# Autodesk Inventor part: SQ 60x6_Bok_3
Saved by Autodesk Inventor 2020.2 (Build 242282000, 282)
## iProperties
Created: 2006-08
Part Number: SQ 60x6_Bok_3
Material: Ogólny
Document SubType Name: Modeling
Designer: F.Stasiak
Manufacturer: Standard
Standards Organization: Custom
Stock Number: DIN EN 10210-2 SQ 60x6
Density: 1 g/cm^3
Appearance: Domyślna
Manager: www.cadconsulting.pl
Company: Fabian Stasiak CAD Consulting
G_L: 767,1 mm
G_W: 60,000 mm
G_H: 60,000 mm
AFG_Item: 60 x 60 x 6
Author: F.Stasiak
Subject: Zbiór ćwiczeń. Autodesk Inventor 2020. Kurs podstawowy
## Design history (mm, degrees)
sketch "AFG_Detailed"
  geometry: L1 (-12, 54)-(-48, 54); L2 (-54, 48)-(-54, 12); L3 (-48, 6)-(-12, 6); L4 (-6, 12)-(-6, 48); L5 (-12, 60)-(-48, 60); L6 (-60, 48)-(-60, 12); L7 (-48, 0)-(-12, 0); L8 (0, 12)-(0, 48); A1 r 6 centre (-12, 48) between (-6, 48) and (-12, 54); A2 r 12 centre (-12, 48) between (0, 48) and (-12, 60); A3 r 6 centre (-12, 12) between (-12, 6) and (-6, 12); A4 r 12 centre (-12, 12) between (-12, 0) and (0, 12); A5 r 12 centre (-48, 12) between (-60, 12) and (-48, 0); A6 r 6 centre (-48, 12) between (-54, 12) and (-48, 6); A7 r 6 centre (-48, 48) between (-48, 54) and (-54, 48); A8 r 12 centre (-48, 48) between (-48, 60) and (-60, 48); 4 further points
  constraints: 16 end point, 16 point on circle, 16 tangent, 8 centre point, 6 point on line, 4 parallel, 2 perpendicular, 1 vertical
  dimensions: "d15" = 60 distance of point (-60, 0) point (0, 0) (= GEO_B); "d16" = 6 distance between parallel lines of L7 L3 (= GEO_S); "d17" = 6 distance between parallel lines of L8 L4 (= GEO_S); "d18" = 6 distance between parallel lines of L5 L1 (= GEO_S); "d19" = 6 distance between parallel lines of L6 L2 (= GEO_S); "d20" = 30 distance from line of point (-30, 30) L7 (= 0.5 x GEO_H); "d30" = 6 radius of A1 (= GEO_R1 - GEO_S); "GEO_R1" = 12 radius of A2; "d32" = 6 radius of A3 (= GEO_R1 - GEO_S); "d33" = 12 radius of A4 (= GEO_R1); "d34" = 12 radius of A5 (= GEO_R1); "d35" = 6 radius of A6 (= GEO_R1 - GEO_S); "d36" = 6 radius of A7 (= GEO_R1 - GEO_S); "d37" = 12 radius of A8 (= GEO_R1); "d38" = 30 distance from line of L6 point (-30, 30) (= 0.5 x GEO_B); "d39" = 60 distance between parallel lines of L7 L5 (= GEO_H)
sketch "AFG_Medium"
  geometry: L1 (-6, 54)-(-54, 54); L2 (-54, 54)-(-54, 6); L3 (-54, 6)-(-6, 6); L4 (-6, 6)-(-6, 54); L5 (0, 60)-(-60, 60); L6 (-60, 60)-(-60, 0); L7 (-60, 0)-(0, 0); L8 (0, 0)-(0, 60); 1 further point
  constraints: 16 end point, 4 parallel, 2 perpendicular, 1 vertical
  dimensions: "GEO_B" = 60 distance of L6.end L7.end; "GEO_S" = 6 distance between parallel lines of L7 L3; "d5" = 6 distance between parallel lines of L8 L4 (= GEO_S); "d6" = 6 distance between parallel lines of L5 L1 (= GEO_S); "d7" = 6 distance between parallel lines of L6 L2 (= GEO_S); "d12" = 30 distance from line of point (-30, 30) L7 (= 0.5 x GEO_H); "d40" = 60 distance between parallel lines of L7 L5 (= GEO_H); "d41" = 30 distance from line of L6 point (-30, 30) (= 0.5 x GEO_B)
sketch "AFG_Simplified"
  geometry: L1 (0, 60)-(-60, 60); L2 (-60, 60)-(-60, 0); L3 (-60, 0)-(0, 0); L4 (0, 0)-(0, 60); 1 further point
  constraints: 8 end point, 2 parallel, 1 perpendicular, 1 vertical
  dimensions: "d23" = 60 distance of L2.end L3.end (= GEO_B); "d28" = 30 distance from line of point (-30, 30) L3 (= 0.5 x GEO_H); "d42" = 60 distance between parallel lines of L3 L1 (= GEO_H); "d43" = 30 distance from line of point (-30, 30) L2 (= 0.5 x GEO_B)
derived "Szkielet podstawy.ipt"
  sketch "Szkic1"
    geometry: L1 (0, 0)-(1500, 0) reference; L2 (1500, 0)-(1500, 1000) reference; L3 (1500, 1000)-(0, 1000) reference; L4 (0, 1000)-(0, 0) reference
  sketch "Szkic2"
    geometry: L1 (0, 1000)-(0, 0) reference; L2 (0, 0)-(1500, 0) reference; L3 (1500, 0)-(1500, 1000) reference; L4 (500, 1000)-(1500, 1000) reference; L5 (1500, 1000)-(1500, 0) reference; L6 (1500, 0)-(500, 0) reference; L7 (500, 0)-(500, 1000) reference; L8 (1500, 1000)-(0, 1000) reference
node "AFG_StartWorkPoint_SQ 60x6_Bok_3"
node "AFG_EndWorkPoint_SQ 60x6_Bok_3"
node "AFG_HelpAxis"
node "AFG_HelpStart"
node "AFG_HelpEnd"
node "AFG_Midplane"
  node "AFG_Startplane"
  node "AFG_EndPlane"
node "AFG_Profile_AxisX_for_External_Matrix"
node "SQ 60x6_Spód_4" dims "d53" = 10
node "SQ 60x6_Góra_4" dims "d55" = 10
extrude "AFG_Detailed_SQ 60x6_Bok_3" join sketch "AFG_Detailed" stored distance "d49" = 0.13; taper "d50" = 0 deg
extrude "AFG_Simplified_SQ 60x6_Bok_3" join sketch "AFG_Simplified" stored distance "d51" = 0.13; taper "d52" = 0 deg
node "AFG_STARTCUTPLANE_SQ 60x6_Bok_3"
node "AFG_ENDCUTPLANE_SQ 60x6_Bok_3"
node "Bryła1"
node "Korpusy bryłowe"
node "Korpusy powierzchniowe"
feature "Pozyskana bryła konstrukcyjna1"
body "Srf1"
feature "Pozyskana bryła konstrukcyjna2"
body "Srf2"
feature "DerivedBody::SQ 60x6_Spód_4"
feature "DerivedBody::SQ 60x6_Góra_4"
other parameters: "GEO_H" = 60, "AFG_Origin_X" = 0 (= 0 x GEO_B) [user parameter], "AFG_Origin_Y" = 0 (= 0 x GEO_H) [user parameter], "AFG_IP_X2" = 0 (= 0 x GEO_B) [user parameter], "AFG_IP_Y4" = 0 (= 0 x GEO_H) [user parameter], "AFG_IP_X6" = 0 (= 0 x GEO_B) [user parameter], "AFG_IP_Y8" = 0 (= 0 x GEO_H) [user parameter], "d47" = 0, "d48" = 0, "G_L" = 767.10678 [user parameter], "d54" = 0, "d56" = 0
